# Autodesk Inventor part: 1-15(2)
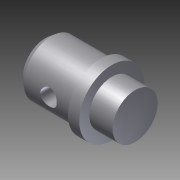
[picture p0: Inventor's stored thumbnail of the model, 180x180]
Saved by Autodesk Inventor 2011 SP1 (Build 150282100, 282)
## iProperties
Created: 2014-02
Part Number: 1-15(2)
Document SubType Name: Modeling
Designer: Administrator
Density: 1 g/cm^3
Author: Administrator
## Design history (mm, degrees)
sketch "草图1"
  geometry: L1 (-10.036, 0)-(-10.036, 4.077); L2 (-10.036, 4.077)-(-8.931, 4.97); L3 (-8.931, 4.97)-(-8.931, 0); L4 (-8.931, 4.97)-(0, 4.97); L5 (0, 4.97)-(0, 5.916); L6 (0, 5.916)-(2.035, 5.916); L7 (2.035, 5.916)-(2.035, 4.077); L8 (2.035, 4.077)-(6.242, 4.077); L9 (-10.036, 0)-(6.242, 0); L10 (6.242, 0)-(6.242, 4.077); C1 r 1.5 at (-5.572, 0); 1 further point
  constraints: 20 end point, 5 parallel, 3 perpendicular, 1 centre point, 1 point on line, 1 vertical
  dimensions: "d1" = 3 diameter of C1
revolve "旋转1" sketch "草图1" stored, may be unused: angle "d0" = 90 deg
node "工作平面1"
sketch "草图2"
  geometry: L1 (0, 5.916)-(0, -5.916) reference; L2 (10.036, 4.077)-(10.036, -4.077) reference; L3 (8.931, 4.97)-(8.931, -4.97) reference; C1 r 1.5 at (4.465, 0); 1 further point
  constraints: 1 centre point
  dimensions: "d3" = 3 diameter of C1
extrude "拉伸1" cut sketch "草图2" stored distance "d4" = 10; taper "d5" = 0 deg
node "实体1"
other parameters: "d2" = -6
